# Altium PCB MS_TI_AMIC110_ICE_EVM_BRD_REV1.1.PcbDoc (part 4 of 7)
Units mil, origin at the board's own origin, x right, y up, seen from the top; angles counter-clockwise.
Board outline 3464.57 x 2204.72 mil, 8 copper layers (TopLayer - S1 (.GTL), MidLayer1 - S2 (.G1), MidLayer2 - S3 (.G2), MidLayer3 - S4 (.G3), MidLayer4 - S5 (.G4), MidLayer5 - S6 (.G5), MidLayer6 - S7 (.G6), BottomLayer - S8 (.GBL)), stack 58.937 mil thick; 504 components, 369 nets, 1811 pads, 874 vias.
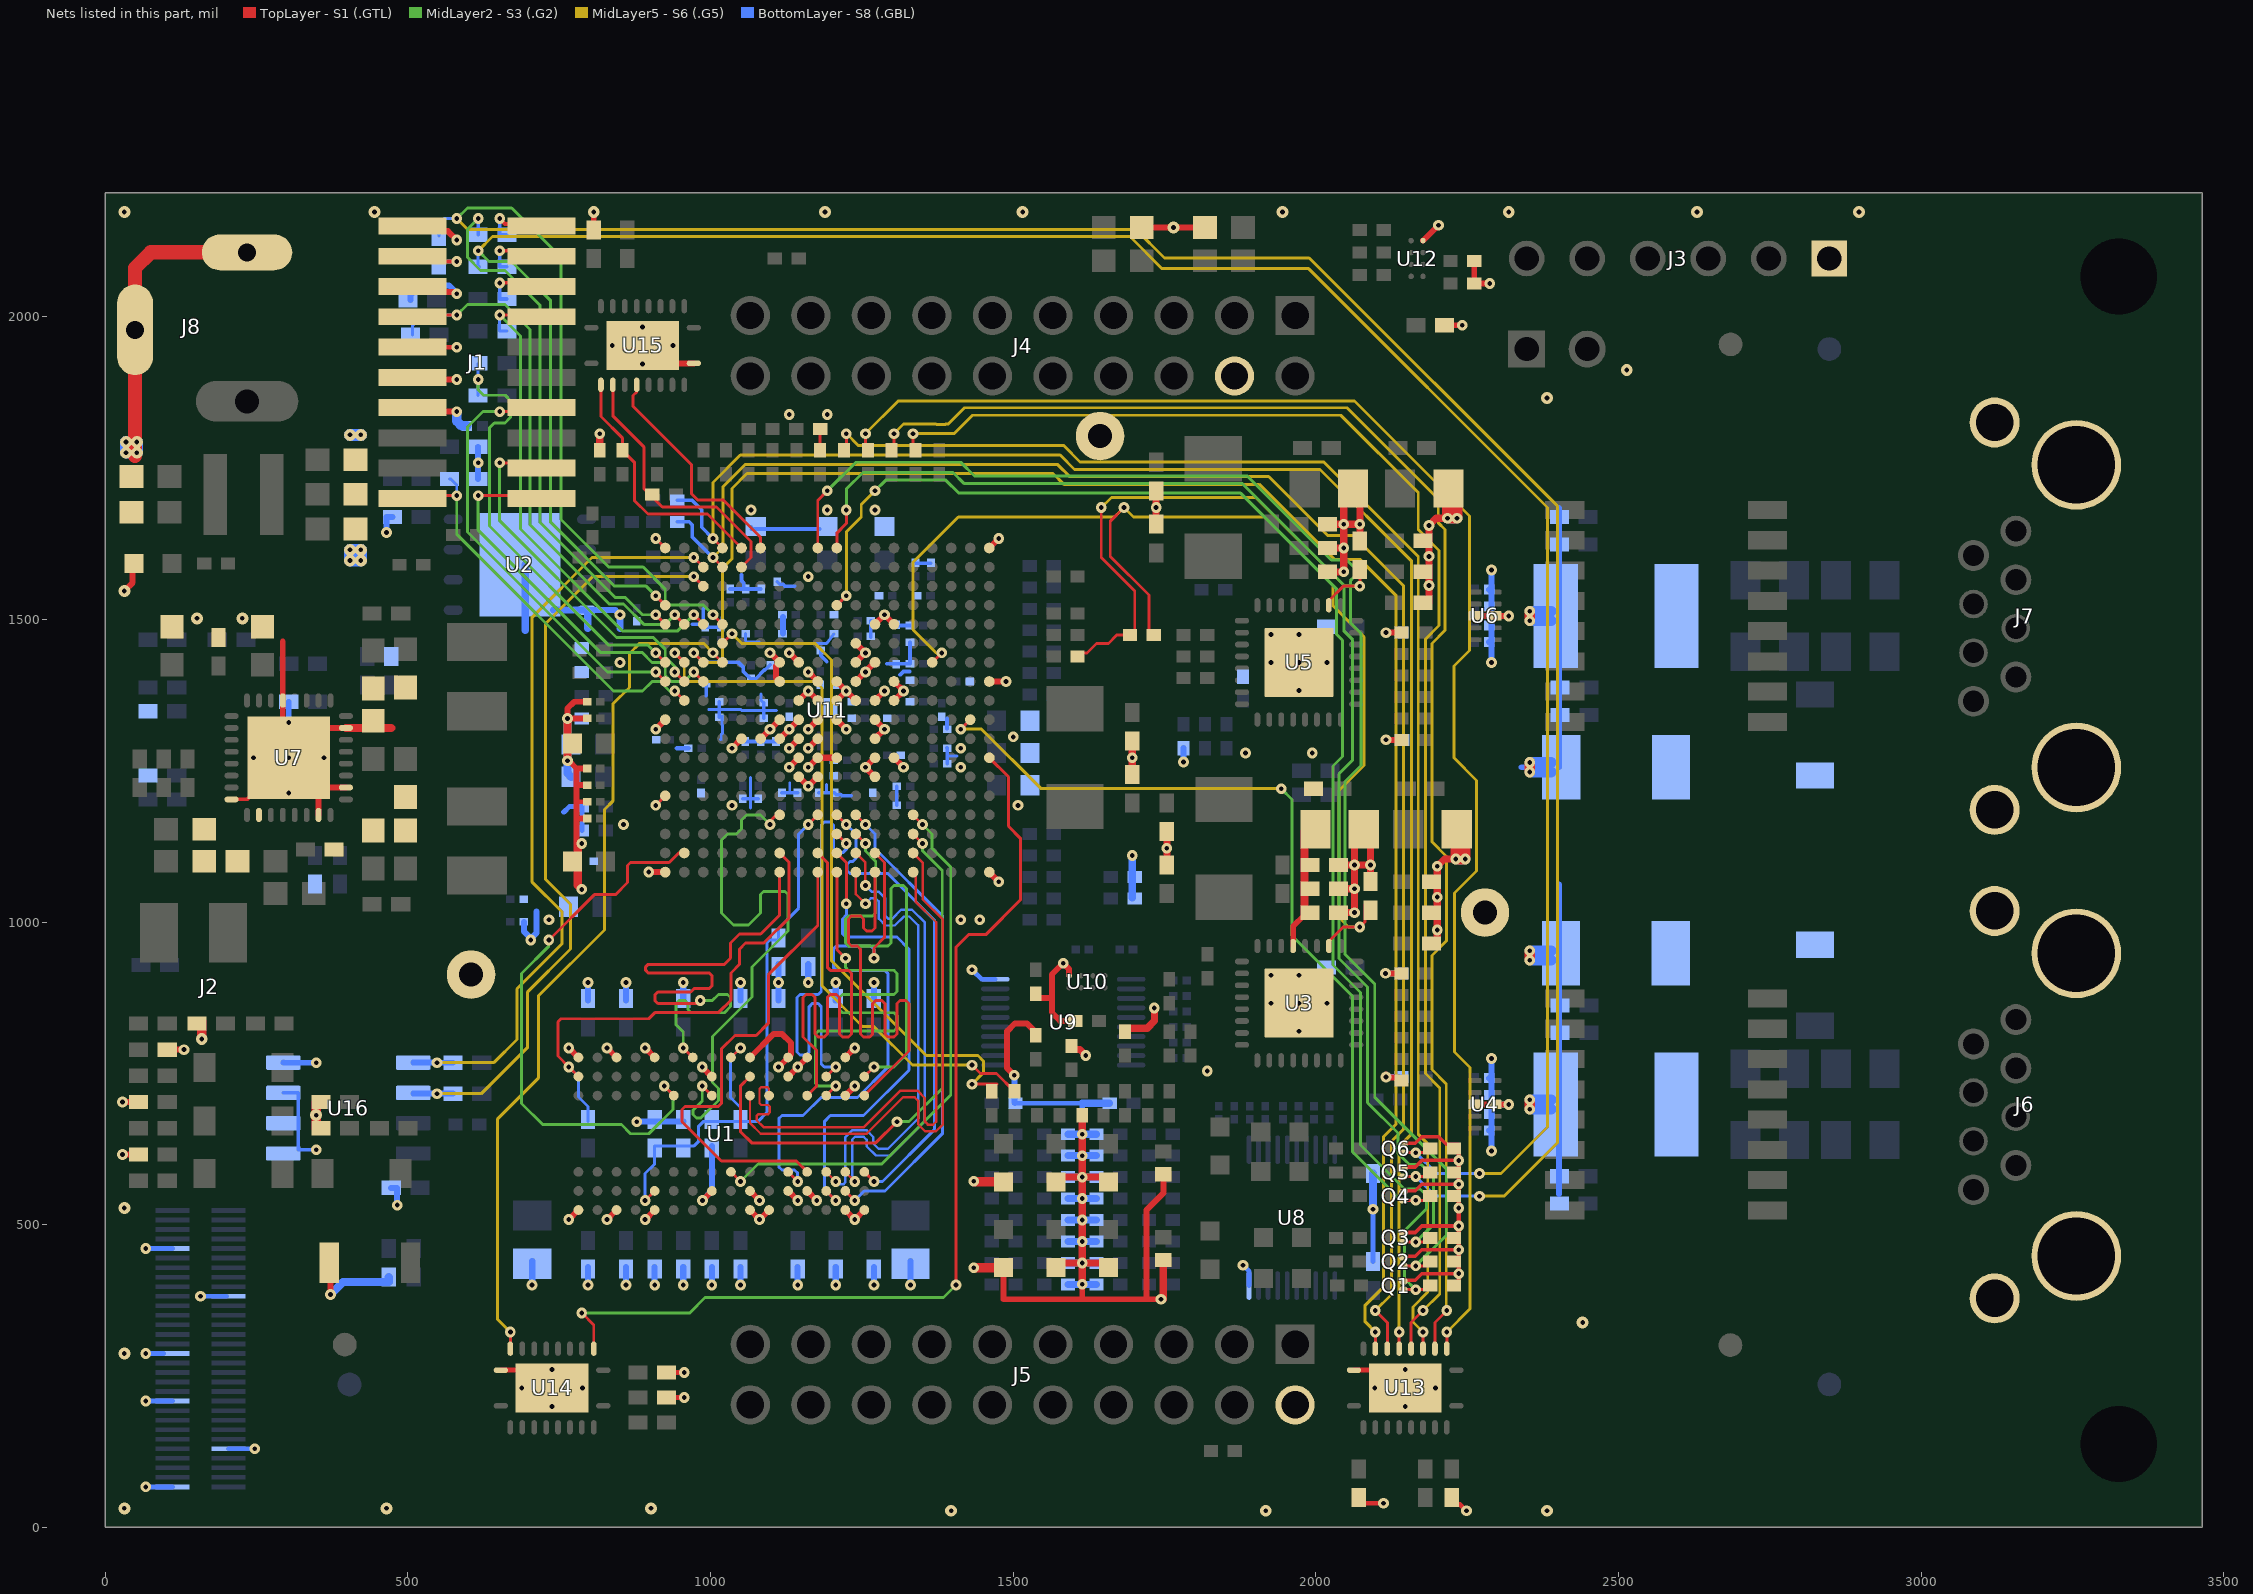
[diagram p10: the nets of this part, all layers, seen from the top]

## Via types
v1: diameter 17.72, hole 7.87, TopLayer - S1 (.GTL) to BottomLayer - S8 (.GBL), 746 vias
v2: diameter 19.68, hole 7.87, TopLayer - S1 (.GTL) to BottomLayer - S8 (.GBL), 128 vias

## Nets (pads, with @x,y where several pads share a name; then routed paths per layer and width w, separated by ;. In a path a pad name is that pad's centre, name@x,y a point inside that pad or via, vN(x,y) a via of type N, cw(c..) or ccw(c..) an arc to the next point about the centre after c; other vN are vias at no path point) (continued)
DDR_D6: U1.G2 U11.P3 | length 916.3
  TopLayer - S1 (.GTL) w4.92: U1.G2@1065.17,744.9 1049.3,729.03 1049.3,654.02 1067.92,635.4 1272.92,635.4 v1(1307.92,670.4) ; U11.P3@1334.65,1145.67 v1(1350.39,1129.92)
  MidLayer2 - S3 (.G2) w4.68: v1(1307.92,670.4) 1327.92,670.4 1382.92,725.4 1382.92,1085.4 1350.42,1117.9 v1(1350.39,1129.92)
DDR_D7: U1.H7 U11.P4 | length 917.4
  TopLayer - S1 (.GTL) w4.92: U1.H7@1033.67,587.4 v1(1049.42,571.65) ; U11.P4@1334.65,1177.17 v1(1350.39,1161.42)
  MidLayer2 - S3 (.G2) w4.68: v1(1049.42,571.65) 1078.17,600.4 1282.92,600.4 1396.93,714.41 1396.93,1091.39 1366.18,1122.14 1366.18,1145.64 v1(1350.39,1161.42)
DDR_D8: U1.D7 U11.J1 | length 799
  TopLayer - S1 (.GTL) w4.92: U1.D7@1159.67,587.4 1141.67,605.4 1017.92,605.4 952.92,670.4 952.92,690.4 957.92,695.4 1012.92,695.4 1017.92,700.4 1017.92,790.4 1040.42,812.9 1075.42,812.9 1095.42,832.9 1095.42,912.9 1177.17,994.65 U11.J1@1177.17,1082.68
DDR_D9: U1.C3 U11.K1 | length 799.4
  TopLayer - S1 (.GTL) w4.92: U1.C3@1191.17,713.41 v1(1206.92,729.15) ; U11.K1@1208.66,1082.68 1208.66,954.66 v1(1222.92,940.4)
  MidLayer2 - S3 (.G2) w4.68: v1(1206.92,729.15) 1177.92,729.15 1172.92,734.15 1172.92,815.4 1177.92,820.4 1302.92,820.4 1307.92,825.4 1307.92,845.4 1302.92,850.4 1217.92,850.4 1212.92,855.4 1212.92,875.4 1217.92,880.4 1302.92,880.4 1307.92,885.4 1307.92,915.4 1302.92,920.4 1227.92,920.4 1222.92,925.4 v1(1222.92,940.4)
DDR_D10: U1.C8 U11.K2 | length 798.9
  TopLayer - S1 (.GTL) w4.92: U1.C8@1191.17,555.9 v1(1206.92,540.15) ; U11.K2@1208.66,1114.17 1224.4,1098.45 v1(1224.4,1030.4)
  BottomLayer - S8 (.GBL) w4.92: v1(1206.92,540.15) 1187.92,559.15 1187.92,670.4 1197.92,680.4 1252.92,680.4 1327.92,755.4 1327.92,955.4 1307.92,975.4 1222.92,975.4 1217.92,980.4 1217.92,1005.4 1224.4,1011.88 v1(1224.4,1030.4)
DDR_D11: U1.C2 U11.K3 | length 797.1
  TopLayer - S1 (.GTL) w4.92: U1.C2@1191.17,744.9 v1(1206.92,760.65) ; U11.K3@1208.66,1145.67 v1(1224.41,1129.92)
  BottomLayer - S8 (.GBL) w4.92: v1(1206.92,760.65) 1187.92,760.65 1182.92,765.65 1182.92,860.4 1177.92,865.4 1167.92,865.4 1162.92,860.4 1162.92,785.4 1157.92,780.4 1147.92,780.4 1142.92,785.4 1142.92,875.4 1147.92,880.4 1177.92,880.4 1182.92,885.4 1182.92,1160.4 1187.92,1165.4 1197.92,1165.4 1202.92,1160.4 1202.92,1120.4 1207.92,1115.4 1219.42,1115.4 1224.42,1120.4 v1(1224.41,1129.92)
DDR_D12: U1.A7 U11.K4 | length 796.4
  TopLayer - S1 (.GTL) w4.92: U11.K4@1208.66,1177.17 v1(1224.41,1161.42) ; U1.A7@1254.17,587.42 v1(1269.92,571.65)
  BottomLayer - S8 (.GBL) w4.92: v1(1224.41,1161.42) 1240.18,1145.64 1240.18,1105.4 1235.18,1100.4 1230.42,1100.4 1225.42,1095.4 1225.42,1085.4 1230.42,1080.4 1292.92,1080.4 1370.42,1002.9 1370.42,657.9 1284.17,571.65 v1(1269.92,571.65)
DDR_D13: U1.A2 U11.L3 | length 795.9
  TopLayer - S1 (.GTL) w4.92: U11.L3@1240.16,1145.67 v1(1255.91,1129.92) ; U1.A2@1254.17,744.9 v1(1269.92,760.65)
  MidLayer2 - S3 (.G2) w4.68: v1(1255.91,1129.92) 1255.92,1117.4 1272.92,1100.4 1272.92,1015.4 1267.92,1010.4 1227.92,1010.4 1222.92,1005.4 1222.92,965.4 1227.92,960.4 1292.92,960.4 1297.92,965.4 1297.92,1055.4 1302.92,1060.4 1318.91,1060.4 1323.91,1055.4 1323.91,781.39 1302.92,760.4 v1@1270.17,760.4
DDR_D14: U1.B8 U11.L4 | length 798.3
  TopLayer - S1 (.GTL) w4.92: U1.B8@1222.67,555.9 v1(1238.42,540.15) ; U11.L4@1240.16,1177.17 v1(1255.91,1161.42)
  BottomLayer - S8 (.GBL) w4.92: v1(1238.42,540.15) 1254.18,555.91 1288.43,555.91 1382.92,650.4 1382.92,1010.4 1271.68,1121.64 1271.68,1145.64 v1(1255.91,1161.42)
DDR_D15: U1.A3 U11.M1 | length 792.6
  TopLayer - S1 (.GTL) w4.92: U1.A3@1254.17,713.41 1327.92,787.15 1327.92,865.4 1322.92,870.4 1312.92,870.4 1307.92,865.4 1307.92,815.4 1302.92,810.4 1292.92,810.4 1287.92,815.4 1287.92,865.4 1282.92,870.4 1272.92,870.4 1267.92,865.4 1267.92,815.4 1262.92,810.4 1252.92,810.4 1247.92,815.4 1247.92,955.4 1242.92,960.4 1232.92,960.4 1227.92,965.4 1227.92,1005.4 1232.92,1010.4 1247.92,1010.4 1252.92,1005.4 1252.92,990.4 1257.92,985.4 1266.67,985.4 1271.67,990.4 1271.67,1050.39 U11.M1@1271.65,1082.68
DDR_DQM0: U1.E7 U11.M2 | length 919.2
  TopLayer - S1 (.GTL) w4.92: U1.E7@1128.17,587.4 v1(1143.92,571.65) ; v1(1269.92,940.4) 1269.92,957.4 1287.43,974.91 1287.43,1098.41 U11.M2@1271.65,1114.17
  BottomLayer - S8 (.GBL) w4.92: v1(1143.92,571.65) 1143.92,585.4 1138.92,590.4 1117.92,590.4 1112.92,595.4 1112.92,675.4 1117.92,680.4 1152.92,680.4 1182.92,710.4 1242.92,710.4 1292.92,760.4 1292.92,915.4 1287.92,920.4 1207.92,920.4 1202.92,925.4 1202.92,955.4 1207.92,960.4 1264.92,960.4 1269.92,955.4 v1(1269.92,940.4)
DDR_DQM1: U1.D3 U11.J2 | length 793.8
  TopLayer - S1 (.GTL) w4.92: U1.D3@1159.67,713.4 1175.4,729.13 1175.4,787.92 1152.92,810.4 1152.92,875.4 1157.92,880.4 1167.92,880.4 1172.92,875.4 1172.92,815.4 1177.92,810.4 1187.92,810.4 1192.92,815.4 1192.92,875.4 1197.92,880.4 1207.92,880.4 1212.92,875.4 1212.92,815.4 1217.92,810.4 1227.92,810.4 1232.92,815.4 1232.92,915.4 1227.92,920.4 1197.92,920.4 1192.92,925.4 1192.92,1098.43 U11.J2@1177.17,1114.17
DDR_DQS0: U1.F3 U11.P1 | length 915.7
  TopLayer - S1 (.GTL) w3.98: U1.F3@1096.67,713.4 1096.67,724.4 1093.67,727.4 1083.92,727.4 1080.92,724.4 1080.92,700.9 1083.92,697.9 1095.17,697.9 1098.17,694.9 1098.17,685.9 1095.17,682.9 1079.17,682.9 1076.17,679.9 1076.17,672.71 1087.48,661.4 1253.36,661.4 1313.6,721.64 1341.68,721.64 1354.16,709.16 1354.16,670.4 1359.16,665.4 1367.92,665.4 1372.92,670.4 1372.92,999.84 1338.78,1033.98 1338.78,1078.55 U11.P1@1334.65,1082.68
DDR_DQS1: U1.C7 U11.L1 | length 797.5
  TopLayer - S1 (.GTL) w3.98: U1.C7@1191.17,587.4 v1(1206.92,571.65) ; U11.L1@1240.16,1082.68 1240.16,1046.17 v1(1255.92,1030.4)
  BottomLayer - S8 (.GBL) w3.98: v1(1206.92,571.65) 1211.42,567.15 1219.92,567.15 1222.92,570.15 1222.92,644.96 1234.36,656.4 1257.48,656.4 1268.92,644.96 1268.92,634.4 1277.92,625.4 1292.92,625.4 1343.16,675.64 1343.16,994.6 1328.36,1009.4 1319.48,1009.4 1304.48,994.4 1289.36,994.4 1277.92,1005.84 1277.92,1034.4 1272.92,1039.4 1264.92,1039.4 v1(1255.92,1030.4)
DDR_DQSN0: U1.G3 U11.P2 | length 915.8
  TopLayer - S1 (.GTL) w3.98: U1.G3@1065.17,713.4 1065.17,668.15 1082.92,650.4 1257.92,650.4 1318.16,710.64 1337.12,710.64 1343.16,704.6 1343.16,665.84 1354.6,654.4 1372.48,654.4 1383.92,665.84 1383.92,1004.4 1350.39,1037.92 1350.39,1098.43 U11.P2@1334.65,1114.17
DDR_DQSN1: U1.B7 U11.L2 | length 798.8
  TopLayer - S1 (.GTL) w3.98: U1.B7@1222.67,587.4 v1(1238.42,571.65) ; U11.L2@1240.16,1114.17 1255.93,1098.41 v1(1255.92,1060.4)
  BottomLayer - S8 (.GBL) w3.98: v1(1238.42,571.65) 1233.92,576.15 1233.92,640.4 1238.92,645.4 1252.92,645.4 1257.92,640.4 1257.92,629.84 1273.36,614.4 1297.48,614.4 1354.16,671.08 1354.16,999.16 1332.92,1020.4 1314.92,1020.4 1299.92,1005.4 1293.92,1005.4 1288.92,1010.4 1288.92,1038.96 1277.48,1050.4 1265.92,1050.4 v1(1255.92,1060.4)
DDR_ODT: U1.K1 U11.G1 | length 942.1
  TopLayer - S1 (.GTL) w4.92: v1(954.92,792.15) U1.K1@970.67,776.4 ; v1@977.92,865.4 912.92,865.4 907.92,870.4 907.92,879.66 912.92,884.66 967.18,884.66 972.92,890.4 997.92,890.4 1002.18,894.66 1002.18,911.88 997.92,916.14 897.1,916.14 892.92,920.32 892.92,926.22 897.1,930.4 1022.92,930.4 1032.92,940.4 1032.92,965.4 1047.92,980.4 1082.92,980.4 1114.19,1011.67 U11.G1@1114.17,1082.68
  MidLayer2 - S3 (.G2) w4.68: v1(954.92,792.15) 954.92,818.4 942.92,830.4 942.92,865.4 947.92,870.4 957.92,870.4 962.92,865.4 962.92,855.4 967.92,850.4 1022.92,850.4 1032.92,860.4 1032.92,875.4 1027.92,880.4 1012.92,880.4 1002.92,870.4 v1(982.92,870.4)
DDR_RASN: U1.J3 U11.G4 | length 945.4
  TopLayer - S1 (.GTL) w4.92: v1(986.42,729.15) U1.J3@1002.17,713.4 ; v1@1095.73,1164.11 1108.78,1177.17 U11.G4@1114.17,1177.17
  MidLayer2 - S3 (.G2) w4.68: v1(986.42,729.15) 986.42,704.65 971.07,689.31 971.07,682.25 976.88,676.44 983.96,676.44 1012.92,705.4 1012.92,725.4 1003.42,734.9 1003.42,810.9 1068.67,876.15 1068.67,926.15 1127.92,985.4 1127.92,1045.4 1122.92,1050.4 1087.43,1050.4 1082.43,1045.4 1082.43,1014.91 1062.92,995.4 1037.92,995.4 1017.92,1015.4 1017.92,1135.64 1027.92,1145.64 1043.16,1145.64 1051.18,1153.66 1051.18,1168.66 1059.66,1177.14 1082.68,1177.14 v1(1098.43,1161.42)
DDR_RESETN: R37.2 U1.T2 U11.G2 | length 815.4
  TopLayer - S1 (.GTL) w4.92: U1.T2@781.67,744.9 v1(765.92,760.65) 747.92,778.65 747.92,835.4 752.92,840.4 897.92,840.4 907.92,850.4 1012.92,850.4 1033.66,871.14 1033.66,916.14 1047.92,930.4 1047.92,955.4 1057.92,965.4 1087.92,965.4 1129.95,1007.43 1129.95,1098.41 U11.G2@1114.17,1114.17
  BottomLayer - S8 (.GBL) w4.92: v1(765.92,760.65) 781.68,744.89 781.68,711.14 797.42,695.4 R37.2@797.42,670.4
DDR_VREF: C5.1 C6.1 C171.1 R34.2 R35.2 U1.H1 U1.M8 U11.J4 | length 1034.6
  TopLayer - S1 (.GTL) w4.92: v1(891.92,540.15) U1.M8@907.67,555.9 ; U1.H1@1033.67,776.4 v1(1049.42,792.15) ; v1(1161.42,1161.42) U11.J4@1177.17,1177.17
  BottomLayer - S8 (.GBL) w4.92: v1(891.92,540.15) 891.92,584.65 907.67,600.4 C6.1@907.67,626.78 907.67,630.4 972.92,630.4 980.42,637.9 980.42,662.9 987.92,670.4 R34.2@1049.42,670.4 ; v1(1049.42,792.15) 1032.92,775.65 1032.92,710.4 1049.42,693.9 R34.2@1049.42,674.02 R34.2@1049.42,670.4 ; v1(1161.42,1161.42) 1145.68,1145.66 1145.68,1023.16 1112.42,989.9 C171.1@1112.42,974.02 1112.42,970.4 1097.92,970.4 1092.92,965.4 1092.92,685.4 1077.92,670.4 R34.2@1049.42,670.4
DDR_WEN: U1.L3 U11.B2 | length 942.4
  TopLayer - S1 (.GTL) w4.92: v1(732.92,970.4) 807.92,1045.4 842.92,1045.4 862.92,1065.4 862.92,1093.55 867.92,1098.55 931.67,1098.55 947.3,1114.18 U11.B2@956.69,1114.17 ; v1(923.42,729.15) U1.L3@939.17,713.4
  MidLayer2 - S3 (.G2) w4.68: v1@732.67,970.15 732.67,960.15 687.92,915.4 687.92,700.4 722.92,665.4 852.92,665.4 867.92,650.4 897.92,650.4 937.92,690.4 937.92,714.65 v1(923.42,729.15)
ECAT_LATCH0: R162.2 U11.D18 U13.6 | length 2772.3
  TopLayer - S1 (.GTL) w4.92: v1(1003.93,1633.86) U11.D18@1019.68,1618.11 ; U13.6@2137.8,295.28 v1(2137.8,322.83)
  MidLayer5 - S6 (.G5) w4.92: v1(1003.93,1633.86) 1003.93,1726.37 1049.21,1771.65 1577.76,1771.65 1601.38,1748.03 2006.89,1748.03 2158.46,1596.46 2158.46,650.59 2137.8,629.92 v1(2137.8,322.83)
  BottomLayer - S8 (.GBL) w5.91: R162.2@944.88,1696.85 969.49,1696.85 985.24,1681.1 985.24,1652.55 v1(1003.93,1633.86)
ECAT_LATCH1: R168.2 U11.D17 U13.7 | length 2751.4
  TopLayer - S1 (.GTL) w4.92: v1(1003.93,1602.36) U11.D17@1019.68,1586.61 ; v1(2098.43,358.27) 2118.11,338.58 U13.7@2118.11,295.28
  MidLayer5 - S6 (.G5) w4.92: v1(1003.93,1602.36) 1020.67,1619.1 1020.67,1719.49 1057.09,1755.91 1573.82,1755.91 1593.5,1736.22 1922.24,1736.22 2019.69,1638.78 2062.01,1638.78 2144.69,1556.1 2144.69,657.48 2125,637.8 2125,384.84 v1(2098.43,358.27)
  BottomLayer - S8 (.GBL) w5.91: R168.2@944.88,1661.42 964.57,1661.41 969.49,1656.5 969.49,1636.81 v1(1003.93,1602.36)
ECAT_SYNC0: R213.2 U11.E18 U15.2 | length 423.6
  TopLayer - S1 (.GTL) w4.92: U15.2@818.9,1887.8 818.9,1835.63 854.33,1800.2 R213.2@854.33,1779.53 874.02,1759.84 874.02,1696.85 896.65,1674.21 995.08,1674.21 U11.E18@1051.18,1618.11
ECAT_SYNC1: R214.2 U11.E17 U15.3 | length 454.8
  TopLayer - S1 (.GTL) w4.92: U15.3@838.58,1887.8 838.58,1836.61 889.76,1785.43 889.76,1716.54 920.28,1686.02 1009.84,1686.02 1066.93,1628.94 1066.93,1602.36 U11.E17@1051.18,1586.61
EMU2R: J1.17 R6.2 | length 95.5
  TopLayer - S1 (.GTL) w5.91: v1(651.57,2109.25) J1.17@708.66,2109.25
  BottomLayer - S8 (.GBL) w5.91: v1(651.57,2109.25) 651.57,2082.68 R6.2@663.39,2082.68
EMU3R: J1.18 R7.2 | length 103.2
  TopLayer - S1 (.GTL) w5.91: J1.18@507.68,2100.2 516.34,2091.54 v1(580.71,2091.54)
  BottomLayer - S8 (.GBL) w5.91: R7.2@554.13,2091.54 v1(580.71,2091.54)
EMU4: R8.1 U11.A14 | length 885.7
  TopLayer - S1 (.GTL) w4.92: v1(909.45,1507.87) U11.A14@925.2,1492.13
  MidLayer2 - S3 (.G2) w4.92: v1(616.14,2162.4) 598.43,2144.68 598.43,2098.43 620.08,2076.77 660.43,2076.77 718.5,2018.7 718.5,1660.43 842.52,1536.42 859.25,1536.42 887.8,1507.87 v1(909.45,1507.87)
  BottomLayer - S8 (.GBL) w5.91: R8.1@616.14,2135.83 v1(616.14,2162.4)
EMU4R: J1.19 R8.2 | length 112.5
  TopLayer - S1 (.GTL) w5.91: v1(651.57,2162.4) 660.43,2153.54 717.32,2153.54 J1.19@720.67,2150.2
  BottomLayer - S8 (.GBL) w5.91: v1(651.57,2162.4) 651.57,2135.83 R8.2@663.39,2135.83
EMU_RSTN: J1.15 R9.2 | length 95.5
  TopLayer - S1 (.GTL) w5.91: v1(651.57,2056.1) J1.15@708.66,2056.1
  BottomLayer - S8 (.GBL) w5.91: v1(651.57,2056.1) 651.57,2029.53 R9.2@663.39,2029.53
ETH1_EARTH: C44.1 C184.2 J6.9 J6.10 J6.11 J6.12 R49.2
ETH2_EARTH: C67.1 C186.2 J7.9 J7.10 J7.11 J7.12 R66.2
FIRMWARE_LOADED: U11.C12 U13.8 | length 2829.9
  TopLayer - S1 (.GTL) w4.92: v1(972.44,1444.88) U11.C12@988.19,1429.13 ; U13.8@2098.43,295.28 v1(2098.43,322.83)
  MidLayer5 - S6 (.G5) w4.92: v1(972.44,1444.88) 988.19,1429.13 1013.78,1429.13 1019.69,1435.04 1019.69,1584.65 1035.43,1600.39 1035.43,1716.54 1060.04,1741.14 1565.94,1741.14 1583.66,1723.43 1906.5,1723.43 2030.51,1599.41 2072.83,1599.41 2132.87,1539.37 2132.87,666.34 2112.2,645.67 2112.2,397.64 2081.69,367.13 2081.69,339.57 v1(2098.43,322.83)
GND: C1.1 C2.1 C3.2 C5.2 C6.2 C7.2 C8.2 C9.2 C10.2 C11.2 C12.2 C13.2 C14.2 C15.2 C16.2 C17.2 C18.2 C19.2 C20.2 C21.2 C22.2 C23.1 C24.1 C25.2 C26.1 C27.2 C28.1 C29.1 C30.1 C31.1 C32.2 C33.2 C34.2 C35.2 C36.2 C37.2 C38.2 C39.2 C40.2 C41.2 C42.2 C43.2 C44.2 C45.2 C46.2 C47.1 C48.2 C49.1 C50.2 C51.1 C52.1 C53.1 C54.1 C55.2 C56.2 C57.2 C58.2 C59.2 C60.2 C61.2 C62.2 C63.2 C64.2 C65.2 C66.2 C67.2 C68.2 C69.1 C70.2 C71.2 C72.1 C73.2 C74.2 C75.2 C76.2 C77.2 C78.2 C79.2 C80.2 C81.2 C82.2 C83.2 C84.2 C85.2 C86.2 C87.2 C88.2 C89.1 C90.1 C91.2 C92.2 C93.2 C94.1 C95.1 C96.1 C97.2 C98.2 C99.2 C100.1 C101.1 C102.1 C103.2 C104.2 C105.2 C106.1 C107.1 C108.1 C109.1 C110.1 C111.1 C112.1 C113.1 C114.1 C115.1 C116.2 C117.2 C118.2 C119.2 C120.2 C121.2 C122.2 C123.2 C124.2 C125.2 C126.2 C127.2 C128.2 C129.2 C130.2 C131.2 C132.2 C133.2 C134.2 C135.2 C136.2 C137.2 C138.2 C139.2 C140.2 C141.2 C142.2 C143.2 C144.2 C145.2 C146.2 C147.2 C148.2 C149.2 C150.2 C151.2 C152.2 C153.2 C154.2 C155.2 C156.2 C157.2 C158.2 C159.2 C160.2 C161.2 C162.2 C163.2 C164.2 C165.2 C166.2 C167.2 C168.2 C169.1 C170.2 C171.2 C172.1 C173.2 C174.2 C175.2 C176.1 C177.2 C178.2 C179.2 C180.2 C181.2 C182.2 C183.2 D2.1 D3.1 D4.1 D5.2 D7.1 D8.1 D9.1 D10.2 D15.1 J1.8 J1.10 J1.12 J1.16 J1.20 J2.2 J2.9 J2.20 J2.30 J2.41 J2.52 J3.1 J4.4 J5.2 J8.2 J8.3 Q1.2 Q2.2 Q3.2 Q4.2 Q5.2 Q6.2 R1.1 R3.1 R14.1 R18.1 R23.1 R24.1 R32.1 R33.1 R35.1 R36.1 R38.2 R47.2 R49.1 R56.1 R63.2 R66.1 R69.1 R72.1 R75.1 R79.1 R85.1 R86.1 R92.1 R97.1 R100.1 R119.1 R120.1 R121.1 R122.1 R123.1 R124.1 R125.1 R126.1 R127.1 R128.1 R129.1 R130.1 R131.1 R132.1 R133.1 R134.1 R135.1 R136.1 R137.1 R141.1 R142.1 R169.1 R170.1 R172.1 R176.1 R177.1 R184.1 R185.1 R188.1 R189.1 R209.2 R210.2 R228.1 R229.1 R230.1 R231.1 R232.1 R233.1 R234.1 R235.1 R236.1 S1.1 TP8.1 TP9.1 TP10.1 U1.A9 U1.B1 U1.B3 U1.B9 U1.D1 U1.D8 U1.E1 U1.E2 U1.E8 U1.F9 U1.G1 U1.G8 U1.G9 U1.J2 U1.J8 U1.M1 U1.M9 U1.P1 U1.P9 U1.T1 U1.T9 U2.4 U2.9 U3.33 U4.3@2263.09,698.82 U4.8@2295.96,698.82 U5.33 U6.3@2263.09,1505.91 U6.8@2295.96,1505.91 U7.2 U7.7 U7.13 U7.24 U7.26 U7.31 U7.33 U8.10 U9.10 U10.D1 U11.A1 U11.A5 U11.A9 U11.A18 U11.E8 U11.F8 U11.G8 U11.G9 U11.G11 U11.G12 U11.H6 U11.H7 U11.H8 U11.H9 U11.H10 U11.H12 U11.J6 U11.J7 U11.J8 U11.J9 U11.J10 U11.J11 U11.K7 U11.K9 U11.K10 U11.K11 U11.L10 U11.L11 U11.L12 U11.L13 U11.M6 U11.M7 U11.M8 U11.M9 U11.M10 U11.M12 U11.M14 U11.N7 U11.N10 U11.N11 U11.N14 U11.V1 U11.V11 U11.V18 U12.D1 U13.10 U13.21 U14.10 U14.21 U15.10 U15.21 U16.1 U16.2 U16.3 U16.4 | length 15312
  TopLayer - S1 (.GTL) w4.92: v1(909.45,1192.91) U11.A5@925.2,1208.66 ; v1(909.45,1633.86) U11.A18@925.2,1618.11
  TopLayer - S1 (.GTL) w5.91: U7.24@208.66,1202.76 234.25,1202.76 v2(303.15,1271.65) ; Q2.2@2144.69,445.87 Q2.2@2144.69,447.83 ; Q1.2@2146.65,408.46 2164.37,408.46 2175.2,419.29 v1(2236.22,419.29) ; Q2.2@2146.65,447.83 2164.37,447.83 2175.2,458.66 v1(2236.22,458.66) ; Q3.2@2146.65,487.2 2164.37,487.2 2175.2,498.03 v1(2236.22,498.03) ; Q4.2@2146.65,556.1 2164.37,556.1 2175.2,566.93 v1(2236.22,566.93) ; Q5.2@2146.65,595.47 2164.37,595.47 2175.2,606.3 v1(2236.22,606.3) ; Q6.2@2146.65,634.84 2164.37,634.84 2175.2,645.67 2202.76,645.67 2215.55,632.87 R33.1@2234.25,632.87
  TopLayer - S1 (.GTL) w7.87: J1.12@507.68,1950.2 508.07,1949.8 v1(580.71,1949.8) ; U14.10@653.54,259.84 738.19,259.84 U14.21@738.19,230.32 ; C174.2@927.17,214.57 v1(956.69,214.57) ; R177.1@927.17,255.91 v1(956.69,255.91) ; 1563.98,858.27 1564.96,857.28 ; U13.10@2062.99,259.84 2118.11,259.84 U13.21@2147.64,230.32 ; R176.1@2070.87,49.21 2080.26,39.82 v1(2112.05,39.82) ; C173.2@2224.41,49.21 2224.41,38.39 2238.19,38.39 v1(2249.02,27.56) ; R14.1@2236.22,403.54 v1(2236.22,419.29) R18.1@2236.22,438.98 ; R18.1@2236.22,442.91 v1(2236.22,458.66) R23.1@2236.22,478.35 ; R23.1@2236.22,482.28 v1(2236.22,498.03) v1@2236.22,525.59 ; v1(2236.22,527.56) R24.1@2236.22,547.24 ; R24.1@2236.22,551.18 v1(2236.22,566.93) R32.1@2236.22,586.61 ; R32.1@2236.22,590.55 v1(2236.22,606.3) R33.1@2236.22,625.98
  TopLayer - S1 (.GTL) w8: 778.86,1198.82 R228.1@796.06,1198.82 ; v1@1035.43,1287.22 v1(1035.43,1287.4)
  TopLayer - S1 (.GTL) w9.45: U7.33@293.31,1331.69 U7.13@293.31,1366.14 293.31,1463.58 ; U7.31@352.36,1177.17 U7.33@352.36,1211.61 ; U7.33@363.19,1222.44 U7.2@397.64,1222.44 ; U7.33@363.19,1320.87 U7.7@397.64,1320.87
  TopLayer - S1 (.GTL) w9.84: v1(28.54,616.14) C85.2@55.12,616.14 ; v1(28.54,702.76) C83.2@55.12,702.76 ; v2(31.5,1547.24) 45.28,1561.02 D15.1@45.28,1592.52 ; C79.2@102.36,789.37 v1(129.92,789.37) ; S1.1@370.08,437.01 S1.1@372.05,437.01 ; v1(372.05,384.84) S1.1@372.05,437.01 ; S1.1@372.05,437.99 S1.1@372.05,437.01 ; J1.8@507.68,1850.2 514.37,1843.5 v1(580.71,1843.5) ; J1.10@507.68,1900.2 511.22,1896.65 v1(580.71,1896.65) ; J1.16@507.68,2050.2 516.54,2041.34 577.76,2041.34 v1(580.71,2038.39) ; J1.20@507.68,2150.2 516.14,2141.73 565.94,2141.73 v1(580.71,2126.97) ; v1(763.78,1336.61) 763.78,1353.35 774.61,1364.17 R233.1@796.06,1364.17 ; v1@764.76,1267.72 778.54,1253.94 ; v1@766.73,1336.61 R232.1@796.06,1336.61 ; C137.2@778.54,1116.14 778.54,1171.26 ; R230.1@796.06,1171.26 778.54,1171.26 ; R229.1@796.06,1226.38 778.54,1226.38 ; R231.1@796.06,1253.94 778.54,1253.94 ; C175.2@807.09,2143.7 v2(807.09,2173.23) ; U15.21@887.8,1952.76 887.8,1923.23 U15.10@972.44,1923.23 ; D2.1@1484.25,429.13 1484.25,376.97 1614.17,376.97 ; v1(1501.97,747.05) 1490.16,758.86 1490.16,819.88 1502.95,832.68 1522.64,832.68 1537.4,817.91 R188.1@1537.4,812.99 ; R121.1@1537.4,877.95 1537.4,875 1563.98,875 ; v1@1579.72,929.13 1563.98,913.39 1563.98,875 ; v1(1582.68,932.09) 1592.52,922.24 U10.D1@1592.52,911.42 ; C90.1@1598.43,836.61 1577.76,836.61 1563.98,850.39 1563.98,858.27 1563.98,875 ; v1(1614.17,401.57) 1614.17,376.97 ; R185.1@1712.6,2147.64 1750,2147.64 v2(1764.76,2147.64) R184.1@1816.93,2147.64 ; v1(1744.09,376.97) 1720.47,376.97 ; D10.2@1748.03,583.66 1748.03,552.17 1720.47,524.61 1720.47,376.97 ; U12.D1@2177.17,2125.98 v1(2202.76,2151.57) ; C172.1@2212.6,1986.22 v1(2242.13,1986.22) ; R172.1@2261.81,2092.52 R170.1@2261.81,2055.12 v1(2287.4,2055.12) ; 778.54,1171.26 778.54,1226.38 ; 778.54,1226.38 778.54,1253.94 ; 1614.17,376.97 1720.47,376.97
  TopLayer - S1 (.GTL) w10: v1(765.92,508.65) U1.T9@781.67,524.4 ; v1(765.92,792.15) U1.T1@781.67,776.4 ; v1(828.92,508.65) U1.P9@844.67,524.4 ; v1(828.92,792.15) U1.P1@844.67,776.4 ; v1(891.92,508.65) U1.M9@907.67,524.4 ; v1(891.92,792.15) U1.M1@907.67,776.4 ; v1(897.92,1082.68) U11.A1@925.2,1082.68 ; v1(909.45,1318.9) U11.A9@925.2,1334.65 ; v1(986.42,760.65) U1.J2@1002.17,744.9 ; v1(986.56,540.01) U1.J8@1002.31,555.76 ; v1@1035.43,1287.22 1051.06,1302.85 U11.E8@1051.06,1303.26 ; U1.G9@1065.17,524.4 v1(1080.92,508.65) U1.F9@1096.67,524.4 ; U1.G8@1065.17,555.9 v1(1080.92,540.15) ; U1.G1@1065.17,776.4 1104.17,815.4 1117.92,815.4 1132.92,800.4 1132.92,781.15 v1(1112.42,760.65) ; U11.F8@1082.68,1303.15 v1(1098.43,1318.9) U11.G9@1114.17,1334.65 ; v1(1098.43,1444.88) U11.G12@1114.17,1429.13 1107.92,1422.88 1107.92,1403.9 U11.G11@1114.17,1397.64 ; U11.G8@1114.17,1303.15 U11.H9@1145.68,1334.65 ; U1.E8@1128.17,555.9 v1(1143.92,540.15) ; U1.E2@1128.17,744.9 v1(1143.92,760.65) U1.D1@1159.67,776.4 ; v1(1129.92,1255.91) U11.H7@1145.68,1271.66 ; v1(1129.92,1287.4) U11.H8@1145.68,1303.16 ; v1(1129.92,1444.88) U11.H12@1145.68,1429.14 ; U11.H6@1145.68,1240.16 v1(1161.42,1224.41) U11.J6@1177.17,1240.16 ; U11.H10@1145.68,1366.16 v1(1161.42,1381.89) U11.J10@1177.17,1366.14 ; U1.D8@1159.67,555.9 v1(1175.42,540.15) ; v1(1161.42,1255.91) U11.J7@1177.17,1271.65 U11.K7@1208.66,1271.65 ; v1(1161.42,1287.4) U11.J8@1177.17,1303.15 ; v1(1161.42,1318.9) U11.J9@1177.17,1334.65 ; v1(1161.42,1413.39) U11.J11@1177.17,1397.64 ; U11.K9@1208.66,1334.65 v1(1224.41,1318.9) ; U11.K10@1208.66,1366.14 v1(1224.41,1381.89) ; U11.K11@1208.68,1397.64 v1(1224.41,1381.89) ; U1.B9@1222.67,524.4 v1(1238.42,508.65) U1.A9@1254.17,524.43 ; U1.B3@1222.67,713.4 v1(1238.42,729.15) ; U1.B1@1222.67,776.4 v1(1238.42,792.15) ; U11.L10@1240.16,1366.16 v1(1224.41,1381.89) ; U11.L11@1240.16,1397.64 v1(1255.91,1413.39) U11.M12@1271.65,1429.13 ; U11.L12@1240.16,1429.13 v1(1255.91,1444.88) U11.L13@1240.18,1460.64 ; U11.M6@1271.65,1240.16 v1(1255.91,1255.91) U11.M7@1271.66,1271.64 ; U11.M8@1271.65,1303.15 v1(1287.4,1318.9) U11.M9@1271.65,1334.65 ; U11.M10@1271.65,1366.14 v1(1287.4,1381.89) ; U11.M14@1271.65,1492.13 v1(1287.4,1507.87) ; v1(1287.4,1507.87) U11.N14@1303.15,1492.13 ; U11.N7@1303.15,1271.65 v1(1318.9,1255.91) ; U11.N10@1303.15,1366.14 v1(1318.9,1381.89) U11.N11@1303.15,1397.64 ; U11.V1@1460.63,1082.68 v1(1476.38,1066.93) ; U11.V18@1460.63,1618.11 v1(1476.34,1633.85) ; U11.V11@1460.63,1397.64 v1(1488.19,1397.64) ; v1(2115.16,915.35) C26.1@2141.73,915.35 ; v1@2116.14,748.03 2121.06,743.11 2136.81,743.11 C27.2@2141.73,738.19 ; v1(2116.14,1301.18) C50.2@2141.73,1301.18 C50.2@2142.72,1301.18 ; v1(2116.14,1478.35) C49.1@2142.72,1478.35 ; U4.3@2263.09,698.82 U4.8@2295.96,698.82 v1(2318.9,698.82) ; U6.3@2263.09,1505.91 v1(2318.9,1505.91)
  TopLayer - S1 (.GTL) w11.81: R234.1@816.93,1779.53 v1(816.93,1807.09) ; D8.1@1570.87,570.87 1578.74,578.74 v1(1614.17,578.74) ; D3.1@1571.85,437.01 v1(1614.17,437.01) ; R189.1@1596.46,795.28 1602.36,789.37 1610.24,789.37 v1(1620.08,779.53) ; v1(1614.17,401.57) v1(1614.17,437.01) ; R236.1@1614.17,681.1 v1(1614.17,649.61) v1(1614.17,614.17) v1(1614.17,578.74) ; D4.1@1656.5,437.01 v1(1614.17,437.01) ; D9.1@1657.48,570.87 1649.61,578.74 v1(1614.17,578.74) ; R235.1@1683.07,824.8 1721.46,824.8 1733.27,836.61 v1(1733.27,858.27) ; C168.2@1696.85,1244.09 v1(1696.85,1271.65) C170.2@1696.85,1299.21 ; C69.1@1736.22,1657.48 v1(1736.22,1685.04) C68.2@1736.22,1712.6 ; v1@1748.03,376.97 D5.2@1748.03,441.93 ; C46.2@1753.94,1094.49 v1(1753.94,1122.05) C45.2@1753.94,1149.61 ; C58.2@2019.69,1578.74 v1(2046.26,1578.74) v1(2046.26,1618.11) ; C57.2@2019.69,1618.11 v1(2046.26,1618.11) ; C56.2@2019.69,1657.48 v1(2046.26,1657.48) ; C35.2@2037.4,1015.75 v1(2063.98,1015.75) v1(2063.98,1055.12) ; C34.2@2037.4,1055.12 v1(2063.98,1055.12) ; C33.2@2037.4,1094.49 v1(2063.98,1094.49) ; R69.1@2072.83,1625.98 R69.1@2072.83,1629.92 v1(2072.83,1657.48) ; v1@2073.82,1657.48 v1(2072.83,1657.48) ; R56.1@2090.55,1062.99 R56.1@2090.55,1066.93 v1(2090.55,1094.49) ; v1@2091.54,1094.49 v1(2090.55,1094.49) ; C66.2@2177.17,1527.56 2187.01,1527.56 v1(2187.01,1556.1) C65.2@2187.01,1578.74 ; C65.2@2177.17,1578.74 C65.2@2187.01,1578.74 ; C64.2@2177.17,1629.92 C64.2@2187.01,1629.92 ; v1@2187.01,1657.48 v1(2187.01,1655.51) ; C39.2@2190.94,964.57 2200.79,964.57 v1(2200.79,987.2) C38.2@2200.79,1015.75 ; C38.2@2190.94,1015.75 C38.2@2200.79,1015.75 ; C37.2@2190.94,1066.93 C37.2@2200.79,1066.93 ; v1@2200.79,1094.49 v1(2200.79,1092.52) ; C63.2@2208.66,1736.22 C63.2@2219.13,1736.22 ; v1(2217.52,1667.32) 2198.82,1667.32 v1(2187.01,1655.51) ; v1(2231.3,1104.33) 2212.6,1104.33 v1(2200.79,1092.52) ; v1(1614.17,437.01) v1(1614.17,472.44) v1(1614.17,507.87) v1(1614.17,543.31) v1(1614.17,578.74) ; v1(2046.26,1618.11) v1(2046.26,1657.48) ; v1(2046.26,1657.48) 2046.26,1697.2 2061.65,1712.6 2072.83,1701.42 v1(2072.83,1657.48) ; v1(2046.26,1657.48) v1(2072.83,1657.48) ; v1(2063.98,1055.12) v1(2063.98,1094.49) ; v1(2063.98,1094.49) v1(2090.55,1094.49) ; v1(2063.98,1094.49) 2063.98,1134.21 2079.37,1149.61 2090.55,1138.43 v1(2090.55,1094.49) ; C65.2@2187.01,1578.74 v1(2187.01,1604.33) C64.2@2187.01,1629.92 ; C64.2@2187.01,1629.92 v1(2187.01,1655.51) ; C38.2@2200.79,1015.75 v1(2200.79,1041.34) C37.2@2200.79,1066.93 ; C37.2@2200.79,1066.93 v1(2200.79,1092.52)
  TopLayer - S1 (.GTL) w13.78: U7.7@397.64,1320.87 472.44,1320.87 ; v1(763.78,1266.73) v1(763.78,1336.61) ; v1(787.4,1054.13) 780.51,1061.02 780.51,1123.03 v1(787.4,1129.92)
  TopLayer - S1 (.GTL) w15.75: v2(159.45,807.09) C76.2@159.45,835.63 ; U7.33@253.94,1211.61 U7.33@253.94,1220.47 ; v2(303.15,1271.65) U7.33@352.36,1222.44 ; U7.33@346.46,1320.87 U7.33@363.19,1320.87 ; U7.33@351.38,1222.44 U7.33@352.36,1222.44 ; R85.1@356.3,659.45 348.43,659.45 v2(348.43,681.1) 348.43,702.76 C77.2@356.3,702.76 ; U7.33@363.19,1222.44 U7.33@352.36,1222.44 ; v1(1435.04,429.13) D2.1@1484.25,429.13 ; v1(1435.04,571.85) 1436.02,570.87 D7.1@1484.25,570.87
  TopLayer - S1 (.GTL) w17.72: C63.2@2219.13,1716.54 2217.52,1716.54 v1(2217.52,1667.32) v1(2233.27,1667.32) C63.2@2233.27,1710.63 ; C36.2@2232.91,1153.54 2231.3,1153.54 v1(2231.3,1104.33) v1(2247.05,1104.33) C36.2@2247.05,1147.64 ; v1(2353.35,690.94) v1(2353.35,706.69) ; v1(2353.35,937.01) v1(2353.35,952.76) ; v1(2353.35,1248.03) v1(2353.35,1263.78) ; v1(2353.35,1498.03) v1(2353.35,1513.78)
  TopLayer - S1 (.GTL) w23.62: v2@49.21,1770.67 J8.3@49.21,1978.57 49.21,2080.71 75.08,2106.57 J8.2@234.25,2106.57
  BottomLayer - S8 (.GBL) w4.92: 997.05,1351.38 1014.57,1351.38 1050.2,1351.38 ; 1016.73,1301.38 1017.72,1302.36 1017.72,1310.04 1019.69,1312.01 1019.69,1325.79 1018.7,1326.77 C130.2@1018.7,1340.55 ; 1051.18,1349.41 1087.8,1349.41 1108.86,1349.41 ; 1065.94,1188.98 1065.94,1203.54 1065.94,1239.26 ; 1083.66,1376.97 1083.66,1366.34 C106.1@1087.8,1362.2 ; 1130.91,1213.78 1130.91,1230.32 ; 1159.99,1460.47 1191.71,1460.43 1203.94,1475.84 C167.2@1203.94,1476.38 ; 1191.93,1213.78 1191.93,1227.36 ; 1390.94,1274.61 1407.28,1274.61
  BottomLayer - S8 (.GBL) w5: C165.2@1057.71,1476.49 1057.71,1465.45 1060.69,1462.46 1080.01,1462.46
  BottomLayer - S8 (.GBL) w5.91: U16.3@294.29,717.91 318.9,717.91 318.9,624.02 v1(348.43,624.02) ; 969.49,1492.13 C109.1@988.19,1492.13 ; 988.19,1517.72 C109.1@988.19,1492.13 ; 992.91,1373.99 C107.1@992.91,1393.7 ; 992.91,1431.3 995.08,1429.13 1046.26,1429.13 1053.74,1421.65 1053.74,1414.38 C164.2@1065.65,1402.47 ; C109.1@993.11,1492.13 C109.1@988.19,1492.13 ; C130.2@1014.57,1338.58 1014.57,1351.38 C125.2@1014.57,1364.17 ; 1019.69,1503.94 1019.69,1491.34 1015.75,1487.4 C109.1@991.14,1487.4 990.16,1487.4 988.19,1489.37 C109.1@988.19,1492.13 ; C120.2@1031.5,1550.55 1031.65,1550.39 C110.1@1082.68,1550.39 ; 1051.18,1573.82 1051.18,1564.36 1055.12,1560.42 1055.12,1553.35 C111.1@1058.07,1550.39 ; C116.2@1053.15,1203.54 1065.94,1203.54 C149.2@1078.74,1203.54 ; C134.2@1054.13,1301.53 C134.2@1057.09,1298.58 ; C134.2@1057.09,1298.43 C150.2@1082.68,1298.43 C151.2@1108.27,1298.43 ; C164.2@1066.93,1402.36 1074.46,1402.36 1088.7,1416.6 1089.46,1416.6 ; C115.1@1066.93,1653.54 1066.93,1649.61 C102.1@1180.12,1649.61 ; C119.2@1087.8,1336.61 1087.8,1349.41 C106.1@1087.8,1362.2 ; 1089.8,1416.34 1098.55,1425.08 C163.2@1098.55,1425.38 ; C124.2@1110.24,1562.2 1114.37,1558.07 1120.08,1558.07 1123.03,1555.12 1138.78,1555.12 ; C141.2@1118.11,1213.78 1130.91,1213.78 C140.2@1143.7,1213.78 ; C139.2@1179.13,1213.78 1191.93,1213.78 C138.2@1204.72,1213.78 1207.89,1210.61 1215.83,1210.61 1217.79,1208.66 1232.28,1208.66 ; C117.2@1181.89,1450.79 C117.2@1181.89,1448.82 1181.89,1440.55 1191.93,1430.51 ; C104.2@1264.54,1498.02 C104.2@1264.96,1498.03 ; C103.2@1264.96,1470.47 C104.2@1264.96,1498.03 ; 1272.53,1498.02 C104.2@1264.96,1498.03 ; 1291.34,1427.17 C97.2@1329.53,1427.17 1329.53,1429.98 1329.58,1430.03 1329.58,1453.69 1329.53,1453.74 C98.2@1329.53,1462.6 ; C157.2@1306.43,1491.21 1306.87,1490.96 1308.27,1490.16 C122.2@1329.53,1490.16 ; C114.1@1307.87,1192.91 C113.1@1307.87,1224.41 C113.1@1307.87,1224.41 ; 1312.99,1408.46 1318.7,1414.17 1328.74,1414.17 ; C126.2@1338.58,1593.7 1339.05,1593.24 C127.2@1364.17,1593.24 ; C92.2@1390.75,1288.39 1390.94,1288.19 C92.2@1390.94,1287.4 1390.94,1274.61 C91.2@1390.94,1261.81 ; C118.2@1390.75,1319.88 1390.75,1336.61
  BottomLayer - S8 (.GBL) w7.87: v1(66.93,66.93) J2.2@111.22,66.93 ; v1(66.93,208.66) J2.20@111.22,208.66 ; v1(66.93,287.4) J2.30@96.46,287.4 ; v1(66.93,460.63) J2.52@111.22,460.63 ; v1(157.48,381.89) J2.41@200.79,381.89 ; J2.9@203.74,129.92 v1(247.05,129.92) ; v1@1434.06,921.26 1434.06,919.29 1447.83,905.51 U9.10@1470.47,905.51 ; R120.1@1502.95,700.79 R120.1@1503.94,700.79 1614.17,700.79 ; v1(1879.92,433.07) 1889.76,423.23 U8.10@1889.76,399.61 ; R119.1@2094.49,438.98 v1(2094.49,525.59)
  BottomLayer - S8 (.GBL) w8: 757.26,1182.02 757.94,1182.02 766.86,1190.94 R142.1@787.4,1190.94 R141.1@787.4,1151.57 R141.1@787.4,1151.44 ; 944.66,1287.4 C182.2@963.39,1287.4
  BottomLayer - S8 (.GBL) w9.45: v2(303.15,1329.72) R100.1@303.15,1364.17
  BottomLayer - S8 (.GBL) w9.84: U16.4@294.29,767.91 294.29,767.72 v1(348.43,767.72) ; v1(464.57,1643.7) 464.57,1669.29 C23.1@474.41,1669.29 ; C176.1@472.44,561.02 482.28,561.02 v1(482.28,532.48) ; C2.1@503.94,2027.56 503.94,2035.43 520.67,2052.17 567.91,2052.17 v1@579.72,2040.35 ; R3.1@616.14,1732.28 v1(616.14,1758.86) R1.1@616.14,1785.43 ; C144.2@691.44,1000.4 691.44,984.74 v1@702.76,973.43 ; v1(1501.97,747.05) 1501.97,701.77 R120.1@1502.95,700.79 ; v1(1614.17,401.57) v1(1614.17,437.01) v1(1614.17,472.44) v1(1614.17,507.87) v1(1614.17,543.31) v1(1614.17,578.74) v1(1614.17,614.17) v1(1614.17,649.61) 1614.17,700.79 ; v1(1781.5,1264.76) R72.1@1781.5,1287.4 ; 2339.57,1255.91 R66.1@2387.8,1255.91 ; 2401.57,551.18 2401.57,1062.01 ; R66.1@2401.57,1255.91 2401.57,1358.27 2401.57,1403.54 2401.57,1684.55
  BottomLayer - S8 (.GBL) w10: v1@700.42,972.9 v1(702.92,970.4) 702.92,972.61 712.6,982.28 712.6,1017.72 ; v1@705.42,400.65 C8.2@705.42,440.4 ; 767.92,1090.4 777.92,1100.4 ; U2.4@795.28,1515.55 842.72,1515.55 v1(850.39,1507.87) ; v1(797.42,400.39) C11.2@797.42,430.4 ; C18.2@797.42,870.4 v1(797.42,900.4) ; v1(860.42,400.4) C10.2@860.42,430.4 ; C17.2@860.42,870.4 v1(860.42,900.4) ; v1(877.92,670.4) R35.1@954.92,670.4 ; v1(907.67,400.4) R38.2@907.67,430.4 ; v1(954.92,400.4) R36.1@954.92,430.4 ; C16.2@954.92,870.4 v1(954.92,900.4) ; v1(986.56,540.01) 1002.17,555.9 C5.2@1002.17,626.78 C5.2@1002.17,630.4 ; v1(1002.17,400.4) C9.2@1002.17,430.4 ; v1(1049.42,400.4) C22.2@1049.42,430.4 ; C15.2@1049.42,870.4 v1(1049.42,900.4) ; C14.2@1112.42,870.4 v1(1112.42,900.4) C171.2@1112.42,930.4 ; C166.2@1119.58,1476.88 C101.1@1119.58,1504.44 ; v1(1143.92,400.4) C21.2@1143.92,430.4 ; v1(1161.42,900.4) R169.1@1161.42,930.4 ; v1(1206.92,400.4) C20.2@1206.92,430.4 ; C13.2@1206.92,870.4 v1(1206.92,900.4) ; v1(1269.92,400.4) C19.2@1269.92,430.4 ; C12.2@1269.92,870.4 v1(1269.92,900.4) ; v1(1330.42,400.4) C7.2@1330.42,440.4 ; v1(2115.16,915.35) C24.1@2141.73,915.35 ; v1(2116.14,744.09) C25.2@2141.73,744.09 C25.2@2142.72,744.09 ; v1(2116.14,1301.18) C48.2@2142.72,1301.18 ; C31.1@2286.61,655.51 2290.35,655.51 2290.35,742.13 C28.1@2286.61,742.13 ; v1(2290.35,622.05) C31.1@2290.35,651.77 ; C28.1@2290.35,745.87 v1(2290.35,774.61) ; v1(2290.35,1429.13) 2290.35,1458.86 C54.1@2286.61,1462.6 2290.35,1462.6 2290.35,1549.21 C51.1@2286.61,1549.21 2290.35,1552.95 v1(2290.35,1581.69) ; 2291.34,698.82 v1(2318.9,698.82) ; 2292.32,1505.91 v1(2318.9,1505.91)
  BottomLayer - S8 (.GBL) w11.81: 693.9,1482.28 U2.9@693.9,1590.55 ; U2.9@740.94,1515.55 U2.4@795.28,1515.55 797.05,1513.78 797.05,1485.24 ; 850.39,1485.24 v1(850.39,1507.87) ; R122.1@1590.55,401.57 v1(1614.17,401.57) R123.1@1637.8,401.57 ; R124.1@1590.55,437.01 v1(1614.17,437.01) R125.1@1637.8,437.01 ; R126.1@1590.55,472.44 v1(1614.17,472.44) R127.1@1637.8,472.44 ; R128.1@1590.55,507.87 v1(1614.17,507.87) R129.1@1637.8,507.87 ; R130.1@1590.55,543.31 v1(1614.17,543.31) R131.1@1637.8,543.31 ; R132.1@1590.55,578.74 v1(1614.17,578.74) R133.1@1637.8,578.74 ; R134.1@1590.55,614.17 v1(1614.17,614.17) R135.1@1637.8,614.17 ; R136.1@1590.55,649.61 v1(1614.17,649.61) R137.1@1637.8,649.61 ; 1614.17,700.79 C89.1@1659.45,700.79 ; R210.2@1696.85,1040.35 v1(1696.85,1110.24)
  BottomLayer - S8 (.GBL) w13.78: v1(372.05,384.84) 392.72,405.51 468.5,405.51 C3.2@468.5,413.39 ; C147.2@763.78,1287.4 v1(763.78,1266.73) 763.78,1246.06 C123.2@769.69,1240.16 ; v1(763.78,1336.61) 763.78,1299.21 C147.2@769.69,1293.31 ; v1(2094.49,525.59) C88.2@2094.49,584.65
  BottomLayer - S8 (.GBL) w15.75: v1(580.71,1843.5) 580.71,1827.76 588.58,1819.88 C1.1@597.24,1819.88
  BottomLayer - S8 (.GBL) w17.72: v1(2217.52,1667.32) v1(2233.27,1667.32) ; v1(2231.3,1104.33) v1(2247.05,1104.33) ; v1(2353.35,690.94) C44.2@2388.78,690.94 ; v1(2353.35,706.69) C44.2@2388.78,706.69 ; v1(2353.35,937.01) R49.1@2388.78,937.01 ; v1(2353.35,952.76) R49.1@2388.78,952.76 ; v1(2353.35,1248.03) R66.1@2388.78,1248.03 ; v1(2353.35,1263.78) R66.1@2388.78,1263.78 ; v1(2353.35,1498.03) C67.2@2388.78,1498.03 ; v1(2353.35,1513.78) C67.2@2388.78,1513.78
  BottomLayer - S8 (.GBL) w19.68: v2(34.45,1775.59) v2(52.17,1775.59) v2(52.17,1793.31) v2(34.45,1793.31) v2(34.45,1775.59) ; v2(404.53,1597.44) v2(422.24,1597.44) v2(422.24,1615.16) v2(404.53,1615.16) v2(404.53,1597.44) ; v2(404.53,1805.12) v2(422.24,1805.12) v2(404.53,1805.12)
  other v1: 705.18,400.41 1820.87,753.94 1432.09,921.26 733.27,1003.94 1413.39,1003.94 1444.88,1003.94 856.3,1161.42 1035.43,1192.91 1507.87,1192.91 1413.39,1255.91 1883.86,1279.53 1994.09,1279.53 1413.39,1287.4 1500,1306.1 1129.92,1318.9 850.39,1429.13 1161.42,1570.87 1066.93,1681.1 1192.91,1681.1 1271.65,1681.1 1129.92,1838.58 1192.91,1838.58
  other v2: 1397.64,27.56 1917.32,27.56 2381.89,27.56 31.5,31.5 464.57,31.5 901.57,31.5 738.19,199.8 2147.64,199.8 687.99,230.32 788.39,230.32 2097.44,230.32 2197.83,230.32 738.19,260.83 2147.64,260.83 31.5,287.4 2440.94,338.58 31.5,527.56 1972.44,819.88 1926.18,866.14 1972.44,866.14 2018.7,866.14 1926.18,912.4 1972.44,912.4 303.15,1213.58 245.08,1271.65 361.22,1271.65 1972.44,1382.87 1926.18,1429.13 1972.44,1429.13 2018.7,1429.13 1926.18,1475.39 1972.44,1475.39 151.57,1501.97 226.38,1501.97 2381.89,1866.14 2513.78,1912.4 887.8,1922.24 837.6,1952.76 937.99,1952.76 887.8,1983.27 31.5,2173.23 444.88,2173.23 1188.98,2173.23 1515.75,2173.23 1944.88,2173.23 2318.9,2173.23 2629.92,2173.23 2897.64,2173.23
GPIO1_1: U11.V7 U14.2 | length 1657.5
  TopLayer - S1 (.GTL) w4.68: v1(787.4,354.33) 807.09,334.65 U14.2@807.09,295.28
  TopLayer - S1 (.GTL) w4.92: v1(1405.51,400.59) 1405.51,958.66 1426.18,979.33 1454.72,979.33 1511.81,1036.42 1511.81,1138.78 1492.13,1158.46 1492.13,1240.16 U11.V7@1460.63,1271.65
  MidLayer2 - S3 (.G2) w4.68: v1(787.4,354.33) 965.55,354.33 991.14,379.92 1384.84,379.92 v1(1405.51,400.59)
GPIO2_27: U11.F18 U15.5 | length 373.1
  TopLayer - S1 (.GTL) w4.92: U15.5@877.58,1888.4 877.95,1888.03 U15.5@877.95,1887.8 ; U15.5@877.95,1875.98 872.05,1870.08 872.05,1852.36 968.5,1755.91 968.5,1707.68 978.84,1697.34 1021.16,1697.34 1082.68,1635.83 U11.F18@1082.68,1618.11
GPIO_PHY1_RESETN: R56.2 R212.2 U3.18 U11.R12 | length 1995.4
  TopLayer - S1 (.GTL) w4.68: v1(1683.07,1685.04) 1660.43,1662.4 1660.43,1604.33 1724.41,1540.35 1724.41,1482.28 R212.2@1732.28,1474.41
  TopLayer - S1 (.GTL) w4.92: U11.R12@1366.14,1428.91 U11.R12@1366.14,1429.13 v1(1381.89,1444.88) v1@1381.89,1444.19 ; U3.18@2021.65,960.63 2021.65,968.5 2045.28,992.13 v1(2072.83,992.13) 2081.69,1000.98 2081.69,1029.53 2090.55,1020.67 R56.2@2090.55,1019.68 2084.65,1013.78 R56.2@2084.65,1009.84
  MidLayer5 - S6 (.G5) w4.92: v1(1381.89,1444.88) 1373.03,1444.88 1334.65,1483.27 1334.65,1594.49 1409.45,1669.29 1667.32,1669.29 v1(1683.07,1685.04) 1698.82,1669.29 1915.35,1669.29 2028.54,1556.1 2028.54,1522.64 2079.72,1471.46 2079.72,1258.86 2038.39,1217.52 2038.39,1007.87 2054.13,992.13 v1(2072.83,992.13)
GPIO_PHY2_RESETN: R69.2 R211.1 R212.1 U5.18 | length 929.3
  TopLayer - S1 (.GTL) w4.68: R211.1@1606.3,1438.98 1612.2,1444.88 1622.05,1444.88 1637.8,1460.63 1657.48,1460.63 1671.26,1474.41 R212.1@1692.91,1474.41 1700.79,1482.28 1700.79,1547.24 1645.67,1602.36 v1(1645.67,1685.04)
  TopLayer - S1 (.GTL) w4.92: U5.18@2021.65,1523.62 2021.65,1531.5 2045.28,1555.12 v1(2072.83,1555.12) R69.2@2072.83,1582.68
  MidLayer5 - S6 (.G5) w4.68: v1(1645.67,1685.04) 1662.4,1701.77 1900.59,1701.77 2047.24,1555.12 v1(2072.83,1555.12)
I2C0_SCL: R218.1 U11.C16 U16.6 | length 1294.6
  TopLayer - S1 (.GTL) w4.92: v1(972.44,1570.87) U11.C16@988.19,1555.12
  MidLayer5 - S6 (.G5) w4.92: v1(548.23,716.54) 621.06,716.54 697.83,793.31 697.83,884.84 768.7,955.71 768.7,1029.53 727.36,1070.87 727.36,1493.11 805.12,1570.87 v1(972.44,1570.87)
  BottomLayer - S8 (.GBL) w9.84: U16.6@508.86,716.54 v1(548.23,716.54) ; v1@548.23,717.91 v1(548.23,716.54) ; R218.1@574.8,716.54 v1(548.23,716.54)
I2C0_SDA: R219.1 U11.C17 U16.5 | length 1293.7
  TopLayer - S1 (.GTL) w4.92: v1(972.44,1602.36) U11.C17@988.19,1586.61
  MidLayer5 - S6 (.G5) w4.92: v1(548.23,767.72) 641.73,767.72 680.12,806.1 680.12,889.76 754.92,964.57 754.92,1016.73 704.72,1066.93 704.72,1502.95 804.13,1602.36 v1(972.44,1602.36)
  BottomLayer - S8 (.GBL) w9.84: U16.5@508.86,767.91 548.23,767.91 v1(548.23,767.72) R219.1@574.8,767.72
IRQ: U11.D12 U14.9 | length 1421.6
  TopLayer - S1 (.GTL) w4.68: U14.9@669.29,295.28 v1(669.29,322.83)
  TopLayer - S1 (.GTL) w4.92: v1(1003.93,1444.88) U11.D12@1019.68,1429.13
  MidLayer5 - S6 (.G5) w4.92: v1(669.29,322.83) 647.64,344.49 647.64,674.21 715.55,742.13 715.55,877.95 824.8,987.2 824.8,1186.02 838.58,1199.8 838.58,1360.24 866.14,1387.8 866.14,1443.9 882.87,1460.63 988.18,1460.63 v1(1003.93,1444.88)
JTAG_EMU0: J1.13 R2.1 U11.C14 | length 890.9
  TopLayer - S1 (.GTL) w4.92: v1(651.57,2002.95) J1.13@708.66,2002.95 ; v1(972.44,1507.87) U11.C14@988.19,1492.13
  MidLayer2 - S3 (.G2) w4.92: v1(651.57,2002.95) 686.02,1968.5 686.02,1649.61 854.33,1481.3 945.87,1481.3 v1(972.44,1507.87)
  BottomLayer - S8 (.GBL) w4.92: R2.1@651.57,1976.38 v1(651.57,2002.95) R2.1@651.57,1976.38 ; R2.1@651.57,1976.38 R2.1@663.39,1976.38 R2.1@651.57,1976.38
JTAG_EMU1: J1.14 R11.1 U11.B14 | length 974.1
  TopLayer - S1 (.GTL) w4.92: J1.14@507.68,2000.2 512.8,2000.2 515.55,2002.95 v1(580.71,2002.95) ; v1(940.94,1507.87) U11.B14@956.69,1492.13
  MidLayer2 - S3 (.G2) w4.92: v1(580.71,2002.95) 598.43,2020.67 660.43,2020.67 701.77,1979.33 701.77,1656.5 832.68,1525.59 856.3,1525.59 889.76,1492.13 925.2,1492.13 v1(940.94,1507.87)
  BottomLayer - S8 (.GBL) w4.92: R11.1@507.87,1970.47 507.87,1986.22 524.61,2002.95 v1(580.71,2002.95)
JTAG_TCK: R4.1 R5.1 U11.A12 | length 746.7
  TopLayer - S1 (.GTL) w4.92: v1(909.45,1444.88) U11.A12@925.2,1429.13
  MidLayer2 - S3 (.G2) w4.92: v1(616.14,1896.65) 616.14,1879.22 624.8,1870.56 660.79,1870.56 669.29,1862.05 669.29,1833.66 660.43,1824.8 642.72,1824.8 634.84,1816.93 634.84,1654.53 831.69,1457.68 896.65,1457.68 v1(909.45,1444.88)
  BottomLayer - S8 (.GBL) w4.92: R4.1@616.14,1870.08 v1(616.14,1896.65) R5.1@616.14,1923.23
JTAG_TDI: J1.3 U11.B11 | length 596
  TopLayer - S1 (.GTL) w4.92: v1(651.57,1758.86) 712.01,1758.86 J1.3@720.67,1750.2 ; v1(940.94,1413.39) U11.B11@956.69,1397.64
  MidLayer2 - S3 (.G2) w4.92: v1(651.57,1758.86) 651.57,1663.39 844.49,1470.47 905.51,1470.47 925.2,1450.79 925.2,1437.99 940.94,1422.24 v1(940.94,1413.39)
JTAG_TDO: J1.7 U11.A11 | length 737.9
  TopLayer - S1 (.GTL) w4.92: v1(651.57,1843.5) 713.98,1843.5 J1.7@720.67,1850.2 ; v1(909.45,1413.39) U11.A11@925.2,1397.64
  MidLayer2 - S3 (.G2) w4.92: v1(651.57,1843.5) 624.02,1843.5 598.43,1817.91 598.43,1644.69 829.72,1413.39 v1(909.45,1413.39)
JTAG_TMS: J1.1 U11.C11 | length 660.2
  TopLayer - S1 (.GTL) w4.92: v1(616.14,1704.72) 716.14,1704.72 J1.1@720.67,1700.2 ; v1(972.44,1413.39) U11.C11@988.19,1397.64
  MidLayer2 - S3 (.G2) w4.92: v1(616.14,1704.72) 616.14,1647.64 817.91,1445.87 886.73,1445.87 903.46,1429.13 917.32,1429.13 925.2,1421.26 925.2,1407.48 935.04,1397.64 956.69,1397.64 v1(972.44,1413.39)
JTAG_TRSTN: J1.2 R3.2 U11.B10 | length 675.3
  TopLayer - S1 (.GTL) w4.92: J1.2@507.68,1700.2 512.2,1704.72 v1(580.71,1704.72) ; v1(940.94,1381.89) U11.B10@956.69,1366.14
  MidLayer2 - S3 (.G2) w4.92: v1(580.71,1704.72) 580.71,1640.75 839.57,1381.89 887.8,1381.89 903.54,1397.64 916.34,1397.64 932.09,1381.89 v1(940.94,1381.89)
  BottomLayer - S8 (.GBL) w4.92: R3.2@568.9,1732.28 570.87,1732.28 580.71,1722.44 v1(580.71,1704.72)
LED_1: Q1.1 R14.2 U11.K15 | length 2374.9
  TopLayer - S1 (.GTL) w4.92: U11.K15@1208.68,1523.64 v1(1224.41,1539.37) ; Q1.1@2146.65,392.72 v1(2165.35,392.72) 2182.09,392.72 R14.2@2188.98,399.61
  MidLayer2 - S3 (.G2) w4.92: v1(1271.65,1712.6) 1289.37,1730.32 1388.78,1730.32 1410.43,1708.66 1875.98,1708.66 2034.45,1550.2 2034.45,1475.39 2044.29,1465.55 2044.29,1273.62 2028.54,1257.87 2028.54,929.13 2073.82,883.86 2073.82,631.89 2146.65,559.06 2172.24,559.06 2183.07,548.23 2183.07,526.57 2146.65,490.16 2146.65,411.42 v1(2165.35,392.72)
  MidLayer5 - S6 (.G5) w4.92: v1(1224.41,1539.37) 1224.41,1644.69 1249.02,1669.29 1249.02,1689.96 v1(1271.65,1712.6)
LED_2: Q2.1 R18.2 U11.J18 | length 2374.6
  TopLayer - S1 (.GTL) w4.92: U11.J18@1177.17,1618.11 1177.17,1696.85 v1(1192.91,1712.6) ; Q2.1@2146.65,432.09 v1(2165.35,432.09) 2182.09,432.09 R18.2@2188.98,438.98
  MidLayer2 - S3 (.G2) w4.92: v1(1192.91,1712.6) 1240.16,1759.84 1413.39,1759.84 1436.02,1737.2 1886.81,1737.2 2025.59,1598.43 2051.18,1598.43 2064.96,1584.65 2064.96,1571.85 2057.09,1563.98 2057.09,1495.08 2074.8,1477.36 2074.8,1258.86 2048.23,1232.28 2048.23,946.85 2097.44,897.64 2097.44,710.63 2215.55,592.52 2215.55,482.28 v1(2165.35,432.09)
LED_3: Q3.1 R23.2 U11.K18 | length 2251.2
  TopLayer - S1 (.GTL) w4.92: U11.K18@1208.66,1618.11 1208.66,1642.72 1224.41,1658.46 v1(1224.41,1681.1) v1@1224.41,1683.07 ; Q3.1@2146.65,471.46 v1(2165.35,471.46) 2182.09,471.46 R23.2@2188.98,478.35
  MidLayer2 - S3 (.G2) w4.92: v1(1224.41,1681.1) 1224.41,1715.55 1251.97,1743.11 1400.59,1743.11 1419.29,1724.41 1879.02,1724.41 2046.26,1557.16 2046.26,1481.3 2061.02,1466.54 2061.02,1267.72 2038.39,1245.08 2038.39,939.96 2085.63,892.72 2085.63,701.77 2135.83,651.57 2135.83,618.11 2154.53,599.41 2174.21,599.41 2194.88,578.74 2194.88,500.98 v1(2165.35,471.46)
LED_4: Q4.1 R24.2 U11.U9 | length 1424.4
  TopLayer - S1 (.GTL) w4.92: v1(1413.39,1318.9) U11.U9@1429.13,1334.65 ; Q4.1@2146.65,540.35 v1(2165.35,540.35) 2182.09,540.35 R24.2@2188.98,547.24
  MidLayer2 - S3 (.G2) w4.92: v1(1942.91,1220.47) 1960.63,1202.76 1960.63,977.36 2061.02,876.97 2061.02,620.08 2140.75,540.35 v1(2165.35,540.35)
  MidLayer5 - S6 (.G5) w4.92: v1(1413.39,1318.9) 1447.83,1318.9 1546.26,1220.47 v1(1942.91,1220.47)
LED_5: Q5.1 R7.1 R32.2 U11.D14 | length 4446.4
  TopLayer - S1 (.GTL) w4.92: v1(1003.94,1507.87) U11.D14@1019.68,1492.13 ; Q5.1@2146.65,579.72 v1(2165.35,579.72) 2182.09,579.72 R32.2@2188.98,586.61
  MidLayer2 - S3 (.G2) w4.92: v1(580.71,2162.4) 598.27,2179.96 671.42,2179.96 752.95,2098.43 752.95,1665.35 831.69,1586.61 888.78,1586.61 925.2,1550.2 925.2,1529.53 931.1,1523.62 988.19,1523.62 v1(1003.94,1507.87)
  MidLayer5 - S6 (.G5) w4.92: v1(580.71,2162.4) 598.43,2144.68 1702.76,2144.68 1750,2097.44 1989.17,2097.44 2399.61,1687.01 2399.61,635.83 2311.02,547.24 v1(2270.67,547.24)
  BottomLayer - S8 (.GBL) w4.92: R7.1@551.18,2133.86 551.18,2153.54 560.04,2162.4 v1(580.71,2162.4) ; v1(2165.35,579.72) 2197.83,547.24 v1(2270.67,547.24)
LED_6: Q6.1 R6.1 R33.2 U11.A15 | length 4087.9
  TopLayer - S1 (.GTL) w4.92: v1(909.45,1539.37) U11.A15@925.2,1523.62 ; Q6.1@2146.65,619.09 v1(2165.35,619.09) 2182.09,619.09 R33.2@2188.98,625.98
  MidLayer2 - S3 (.G2) w4.92: v1(616.14,2109.25) 633.86,2091.54 671.26,2091.54 735.24,2027.56 735.24,1661.42 841.54,1555.12 893.7,1555.12 v1(909.45,1539.37)
  MidLayer5 - S6 (.G5) w4.92: v1(616.14,2109.25) 639.76,2132.87 1692.91,2132.87 1746.06,2079.72 1988.19,2079.72 2382.87,1685.04 2382.87,661.42 2306.1,584.65 v1(2270.67,584.65)
  BottomLayer - S8 (.GBL) w4.92: v1(616.14,2109.25) 616.14,2084.65 R6.1@618.11,2082.68 ; v1(2165.35,619.09) 2199.8,584.65 v1(2270.67,584.65)
LED_ERROR: R28.1 U11.D13 | length 1108.6
  TopLayer - S1 (.GTL) w4.92: U11.D13@1019.69,1460.67 v1(1035.43,1476.38) ; v1(1432.09,732.28) 1473.43,732.28
  MidLayer5 - S6 (.G5) w4.92: v1(1035.43,1476.38) 1051.18,1460.63 1172.24,1460.63 1199.8,1433.07 1199.8,936.02 1356.3,779.53 1441.93,779.53 1450.79,770.67 1450.79,750.98 v1(1432.09,732.28)
LED_RUN: R19.2 U11.B12 | length 1185.3
  TopLayer - S1 (.GTL) w4.92: v1(940.94,1444.88) U11.B12@956.69,1429.13 ; v1(1432.09,763.78) 1445.87,750 1472.44,750 R19.2@1501.97,720.47
  MidLayer5 - S6 (.G5) w4.68: v1(940.94,1444.88) 956.69,1429.13 956.69,1405.51 964.57,1397.64 1173.23,1397.64 1184.06,1386.81 1184.06,894.92 1251.22,827.76 1269.69,827.76 1333.66,763.78 v1(1432.09,763.78)
MCASP1_ACLKR_MCLKXB: R139.2 U13.4 | length 2390.8
  TopLayer - S1 (.GTL) w4.68: R139.2@1220.47,1779.53 1224.41,1783.46 v1(1224.41,1807.09) ; U13.4@2177.17,295.28 v1(2177.17,322.83)
  MidLayer5 - S6 (.G5) w4.68: v1(1224.41,1807.09) 1244.09,1787.4 1583.66,1787.4 1610.61,1760.45 2013.17,1760.45 2169.29,1604.33 2169.29,649.61 2185.04,633.86 2185.04,388.78 2160.43,364.17 2160.43,339.57 v1(2177.17,322.83)
MCASP1_ACLKX_MCLKRB: R12.1 R148.2 | length 35.4
  TopLayer - S1 (.GTL) w4.68: R148.2@1181.1,1779.53 R12.1@1181.1,1814.96
MCASP1_AXR0_MDRB: R143.2 U13.3 | length 2465.2
  TopLayer - S1 (.GTL) w4.68: R143.2@1299.21,1779.53 1303.15,1783.46 v1(1303.15,1807.09) ; U13.3@2196.85,295.28 2196.85,338.58 v1(2216.54,358.27)
  MidLayer5 - S6 (.G5) w4.68: v1(1303.15,1807.09) 1318.9,1822.83 1372.74,1822.83 1373.61,1821.97 1387.78,1821.97 1388.65,1822.83 1392.72,1822.83 1419.67,1849.78 2051.79,1849.78 2202.38,1699.19 2202.38,1659.82 2213.58,1648.62 2213.58,1482.28 2191.93,1460.63 2191.93,1132.87 2216.16,1108.64 2216.16,969.34 2191.93,945.11 2191.93,756.3 2215.55,732.68 2215.55,359.25 v1(2216.54,358.27)
MCASP1_AXR1_MDXB: R140.2 U13.2 | length 2572
  TopLayer - S1 (.GTL) w4.68: v1(1255.91,1807.09) 1255.91,1783.46 R140.2@1259.84,1779.53 ; U13.2@2216.54,295.28 v1(2216.54,322.83)
  MidLayer5 - S6 (.G5) w4.68: v1(1255.91,1807.09) 1310.04,1861.22 2063.98,1861.22 2253.94,1671.26 2253.94,1448.82 2228.35,1423.23 2228.35,1271.65 2265.75,1234.25 2265.75,1084.65 2229.33,1048.23 2229.33,785.43 2254.92,759.84 2254.92,361.22 v1(2216.54,322.83)
MCASP1_FSR_MFSXB: R146.2 U13.5 | length 2396.8
  TopLayer - S1 (.GTL) w4.68: v1(1334.65,1807.09) 1334.65,1783.46 R146.2@1338.58,1779.53 ; U13.5@2157.48,295.28 2157.48,338.58 v1(2177.17,358.27)
  MidLayer5 - S6 (.G5) w4.68: v1(1334.65,1807.09) 1402.56,1807.09 1433.07,1837.6 2041.34,1837.6 2169.29,1709.65 2169.29,1648.62 2203.74,1614.17 2203.74,1490.16 2181.1,1467.52 2181.1,749.81 2204.72,726.19 2204.72,385.83 v1(2177.17,358.27)
NetC32_1: C32.1 C33.1 C34.1 C35.1 R41.1 U3.21 | length 196.7
  TopLayer - S1 (.GTL) w9.45: U3.21@1962.6,960.63 1962.6,993.11 C35.1@1981.3,1011.81
  TopLayer - S1 (.GTL) w13.78: C35.1@1981.3,1011.81 1981.3,1055.12 C32.1@1981.3,1149.61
